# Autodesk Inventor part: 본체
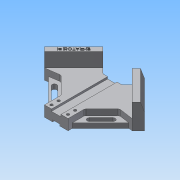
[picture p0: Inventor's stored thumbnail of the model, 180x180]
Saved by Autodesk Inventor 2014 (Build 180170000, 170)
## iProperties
Created: 2020-05
Part Number: 본체
Material: 알루미늄 6061
Document SubType Name: Modeling
Designer: net
Density: 2.71 g/cm^3
Appearance: 알루미늄 - 평지
Mass: 571.604 g
Surface Area: 407.992 cm^2
Volume: 210.924 cm^3
Author: net
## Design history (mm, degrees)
sketch "스케치1"
  geometry: L1 (-84.853, 0)-(84.853, 0); L2 (0, -84.853)-(0, 84.853); L3 (-84.853, 0)-(0, 84.853); L4 (84.853, 0)-(0, 84.853); L5 (-84.853, 0)-(0, -84.853); L6 (0, -84.853)-(84.853, 0); L7 (-35.355, 49.497)-(-16.005, 30.147); L8 (-16.005, 30.147)-(16.005, 30.147); L9 (16.005, 30.147)-(35.355, 49.497); L10 (-20, -64.853)-(20, -64.853); L11 (20, -64.853)-(20, -36.569); L12 (20, -36.569)-(49.497, -7.071); L13 (-20, -64.853)-(-20, -36.569); L14 (-20, -36.569)-(-49.497, -7.071); L15 (68.059, -9.723)-(20, -57.782); L16 (-68.059, -9.723)-(-20, -57.782); L17 (74.246, -10.607)-(24.749, 38.891); L18 (-74.246, -10.607)-(-24.749, 38.891); L19 (-49.497, -7.071)-(-74.246, -10.607); L20 (49.497, -7.071)-(63.64, -21.213); L21 (49.497, -7.071)-(74.246, -10.607); L22 (-49.497, -7.071)-(-63.64, -21.213); 2 further points
  constraints: 44 end point, 14 perpendicular, 14 point on line, 4 parallel, 2 midpoint, 1 coincident, 1 horizontal
  dimensions: "d0" = 120 distance of L1.end L2.end; "d1" = 50 distance from line of L2.end L7; "d2" = 50 distance from line of L9 L2.end; "d3" = 20 distance from line of L2.start L10; "d5" = 95 distance between parallel lines of L10 L8; "d7" = 15 distance of L1.end L17.start; "d8" = 15 distance of L18.start L1.start; "d9" = 20 distance between parallel lines of L5 L14; "d10" = 20 distance between parallel lines of L6 L12; "d11" = 5 distance between parallel lines of L6 L15; "d12" = 5 distance between parallel lines of L5 L16; "d64" = 30 distance of L1.end L20.end; "d65" = 30 distance from line of L1.start L22
extrude "돌출1" new body sketch "스케치1" distance "d13" = 18; taper "d14" = 0 deg
extrude "돌출2" join sketch "스케치1" distance "d15" = 8; taper "d16" = 0 deg
extrude "돌출3" join sketch "스케치1" distance "d17" = 42; taper "d18" = 0 deg
sketch "스케치3"
  geometry: L1 (0, 0)-(-15, 0) reference; L2 (0, 42)-(0, 0) reference; L3 (0, 15)-(-5, 0); 1 further point
  constraints: 2 end point, 2 point on line
  dimensions: "d23" = 5 distance of L1.start L3.end; "d24" = 15 distance of L1.start L3.start
extrude "돌출5" cut sketch "스케치3" stored distance "d25" = 42; taper "d26" = 0 deg
sketch "스케치4"
  geometry: L1 (0, 0)-(40, 0) reference; L2 (0, 18)-(40, 18) reference; L3 (20, 0)-(104.853, 0) reference; L4 (-64.853, 0)-(20, 0) reference; L5 (12, 18)-(12, 14.5); L6 (12, 14.5)-(28, 14.5); L7 (28, 14.5)-(28, 18); L8 (14, 0)-(14, 3); L9 (14, 3)-(26, 3); L10 (26, 3)-(26, 0); 5 further points
  constraints: 12 end point, 6 perpendicular, 4 midpoint, 4 point on line, 2 vertical alignment
  dimensions: "d27" = 16 distance of L5.end L6.end; "d28" = 12 distance of L8.end L9.end; "d29" = 3 distance of L9.end L10.end; "d30" = 3.5 distance of L6.end L7.end
extrude "돌출6" cut sketch "스케치4" stored distance "d31" = 42; taper "d32" = 0 deg
sketch "스케치5"
  geometry: L1 (-8, -64.853)-(-8, 30.147) reference; L2 (-8, 30.147)-(-16.005, 30.147) reference; L3 (-16.005, 30.147)-(-24.749, 38.891) reference; L4 (-24.749, 38.891)-(-74.246, -10.607) reference; L5 (-74.246, -10.607)-(-49.497, -7.071) reference; L6 (-49.497, -7.071)-(-20, -36.569) reference; L7 (-20, -36.569)-(-20, -64.853) reference; L8 (-20, -64.853)-(-8, -64.853) reference; 2 further points
  dimensions: "d33" = 6 distance from line of L8 point (-14, -58.853); "d34" = 6 distance from line of L7 point (-14, -58.853)
sketch "스케치6"
  geometry: L1 (20, -64.853)-(6, -64.853) reference; L2 (20, -36.569)-(20, -57.782) reference; 3 further points
  constraints: 1 coincident
  dimensions: "d35" = 6 distance from line of L2 point (14, -58.853); "d36" = 6 distance from line of L1 point (14, -58.853)
hole "구멍1" sketch "스케치6" at (14, -58.853) diameter "d37" = 4.5; stored, may be unused: countersink angle "d41" = 90 deg, drill point angle "d43" = 118 deg; dims "d38" = 6, "d39" = 8, "d40" = 10, "d42" = 8
sketch "스케치7"
  geometry: L1 (20, -36.569)-(49.497, -7.071) reference; L2 (49.497, -18.385)-(29.698, -38.184); L3 (52.326, -21.213)-(32.527, -41.012); L4 (26.87, -35.355)-(46.669, -15.556); L5 (74.246, -10.607)-(84.853, 0) reference; L6 (35.355, 49.497)-(84.853, 0) reference; A1 r 4 centre (49.497, -18.385) between (52.326, -21.213) and (46.669, -15.556); A2 r 4 centre (29.698, -38.184) between (26.87, -35.355) and (32.527, -41.012); 4 further points
  constraints: 8 end point, 4 point on circle, 4 tangent, 2 centre point, 2 parallel, 1 midpoint
  dimensions: "d50" = 28 distance of L2.start L2.end; "d52" = 12 distance from line of L5 point (39.598, -28.284); "d53" = 38 distance from line of L6 L2.start; "d61" = 4 radius of A1
extrude "돌출7" cut sketch "스케치7" distance "d54" = 10; taper "d55" = 0 deg
sketch "스케치8"
  geometry: L1 (-74.246, -10.607)-(-24.749, 38.891) reference; L2 (-24.749, 38.891)-(-31.82, 45.962) reference; L3 (-44.194, 30.052)-(-65.407, 8.839); L4 (-84.853, 0)-(-35.355, 49.497) reference; L5 (-49.497, 14.142)-(-60.104, 24.749); 2 further points
  constraints: 4 end point, 4 midpoint, 1 perpendicular, 1 other
  dimensions: "d57" = 7.5 distance between parallel lines of L1 L3; "d58" = 30 distance of L3.start L3.end
feature "엠보싱1" sketch "스케치8" dims "d59" = 0.5, "d60" = 0
sketch "스케치9"
  geometry: L1 (0, 42)-(0, 0) reference; L2 (15, 0)-(0, 0) reference; L3 (5, 0)-(0, 15); 1 further point
  constraints: 2 end point, 2 point on line
  dimensions: "d66" = 15 distance of L1.end L3.end; "d67" = 5 distance of L1.end L3.start
extrude "돌출8" cut sketch "스케치9" stored distance "d68" = 10; taper "d69" = 0 deg
extrude "돌출9" cut sketch "스케치1" stored distance "d70" = 10; taper "d71" = 0 deg
fillet "모깎기1" dims "d72" = 5
fillet "모깎기2" dims "d73" = 5
node "솔리드1"
pattern_linear "직사각형 패턴1" dims "d46" = 12, "d49" = 28
mirror "대칭1"
